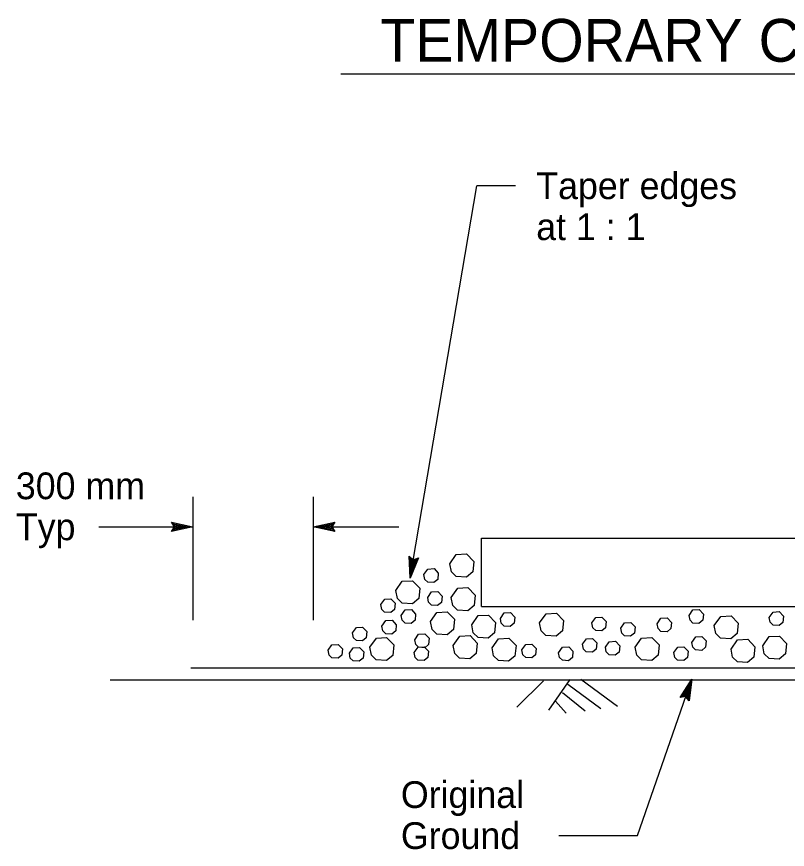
# Model space of a CAD drawing. Extents: x 6707406 to 6714471, y 1868570 to 1872341.
# Drawn here: x 6709477.5 to 6709685, y 1869798.5 to 1870022.7 of the extents above; entities that cross this region are included whole.
import ezdxf

# ---------------------------------------------------------------- set-up
doc = ezdxf.new("R2010")
doc.units = 0
for name, color, linetype in [('56 Stg 3 Anno', 7, 'Continuous'), ('57 Undefined', 7, 'Continuous'), ('59 Soundwall Ann', 7, 'Continuous'), ('60 Nongeo Data', 7, 'Continuous')]:
    doc.layers.add(name, color=color, linetype=linetype)

msp = doc.modelspace()

# ---------------------------------------------------------------- linework, layer by layer
at = {"layer": '56 Stg 3 Anno'}
for p, q in [((6709583.47, 1869871.52), (6709601.41, 1869977.17)), ((6709611.8, 1869977.17), (6709601.41, 1869977.17)), ((6709524.96, 1869893.38), (6709524.96, 1869860.25)), ((6709557.38, 1869893.38), (6709557.38, 1869860.25)), ((6709519.97, 1869885.34), (6709519.2, 1869886.62)), ((6709519.2, 1869886.62), (6709519.2, 1869886.62)), ((6709519.2, 1869886.62), (6709524.96, 1869885.34)), ((6709519.41, 1869886.28), (6709523.64, 1869885.34)), ((6709519.64, 1869885.94), (6709522.31, 1869885.34)), ((6709519.81, 1869885.6), (6709520.99, 1869885.34)), ((6709557.38, 1869885.34), (6709563.14, 1869886.61)), ((6709558.72, 1869885.34), (6709562.92, 1869886.27)), ((6709560.04, 1869885.33), (6709562.75, 1869885.94)), ((6709561.36, 1869885.33), (6709562.52, 1869885.59)), ((6709563.14, 1869886.61), (6709562.38, 1869885.34)), ((6709563.14, 1869886.61), (6709563.14, 1869886.61)), ((6709499.65, 1869885.34), (6709524.96, 1869885.34)), ((6709524.96, 1869885.34), (6709519.2, 1869884.06)), ((6709519.2, 1869884.06), (6709519.97, 1869885.34)), ((6709519.2, 1869884.06), (6709519.2, 1869884.06)), ((6709523.63, 1869885.33), (6709519.43, 1869884.4)), ((6709522.31, 1869885.34), (6709519.6, 1869884.74)), ((6709520.99, 1869885.34), (6709519.82, 1869885.08)), ((6709524.96, 1869885.34), (6709524.96, 1869885.34)), ((6709557.38, 1869885.34), (6709580.43, 1869885.34)), ((6709563.14, 1869884.05), (6709557.38, 1869885.34)), ((6709557.38, 1869885.34), (6709557.38, 1869885.34)), ((6709562.94, 1869884.39), (6709558.71, 1869885.34)), ((6709562.71, 1869884.74), (6709560.04, 1869885.33)), ((6709562.54, 1869885.07), (6709561.36, 1869885.33)), ((6709562.38, 1869885.34), (6709563.14, 1869884.05)), ((6709563.14, 1869884.05), (6709563.14, 1869884.05)), ((6709583.47, 1869871.52), (6709583.17, 1869877.41)), ((6709583.17, 1869877.41), (6709583.17, 1869877.41)), ((6709583.17, 1869877.41), (6709584.3, 1869876.44)), ((6709585.7, 1869876.99), (6709583.47, 1869871.52)), ((6709583.69, 1869872.84), (6709583.48, 1869877.13)), ((6709585.33, 1869876.84), (6709583.69, 1869872.83)), ((6709583.91, 1869874.14), (6709583.78, 1869876.91)), ((6709584.95, 1869876.67), (6709583.91, 1869874.14)), ((6709584.14, 1869875.44), (6709584.08, 1869876.63)), ((6709584.3, 1869876.44), (6709585.7, 1869876.99)), ((6709585.7, 1869876.99), (6709585.7, 1869876.99)), ((6709584.6, 1869876.56), (6709584.14, 1869875.44)), ((6709583.47, 1869871.52), (6709583.47, 1869871.52)), ((6709644.67, 1869802.22), (6709659.29, 1869844.37)), ((6709656.19, 1869839.35), (6709659.29, 1869844.37)), ((6709656.58, 1869839.44), (6709658.85, 1869843.12)), ((6709658.85, 1869843.11), (6709658.36, 1869838.84)), ((6709659.29, 1869844.37), (6709658.61, 1869838.51)), ((6709659.29, 1869844.37), (6709659.29, 1869844.37)), ((6709656.98, 1869839.54), (6709658.42, 1869841.87)), ((6709658.42, 1869841.87), (6709658.1, 1869839.11)), ((6709657.65, 1869839.66), (6709656.19, 1869839.35)), ((6709656.19, 1869839.35), (6709656.19, 1869839.35)), ((6709657.35, 1869839.59), (6709657.98, 1869840.62)), ((6709658.61, 1869838.51), (6709657.65, 1869839.66)), ((6709657.98, 1869840.62), (6709657.84, 1869839.44)), ((6709658.61, 1869838.51), (6709658.61, 1869838.51)), ((6709623.47, 1869802.22), (6709644.67, 1869802.22))]:
    msp.add_line(p, q, dxfattribs=at)
at = {"layer": '57 Undefined'}
msp.add_line((6709564.84, 1870007.33), (6709984.75, 1870007.33), dxfattribs=at)
at = {"layer": '59 Soundwall Ann'}
for p, q in [((6709619.34, 1869843.9), (6709612.17, 1869836.78)), ((6709626.49, 1869844.23), (6709620.7, 1869835.99)), ((6709625.94, 1869843.01), (6709634.84, 1869836.46)), ((6709629.39, 1869844.36), (6709639.34, 1869837.03)), ((6709624.5, 1869840.75), (6709630.61, 1869835.77)), ((6709622.56, 1869838.37), (6709625.47, 1869835.17))]:
    msp.add_line(p, q, dxfattribs=at)
at = {"layer": '60 Nongeo Data'}
for p, q in [((6709602.72, 1869863.92), (6709602.72, 1869882.28)), ((6709602.72, 1869882.28), (6709947.32, 1869882.28)), ((6709602.72, 1869863.92), (6709756.24, 1869863.92)), ((6709524.37, 1869847.39), (6709755.52, 1869847.39)), ((6709502.72, 1869844.14), (6709754.44, 1869844.14))]:
    msp.add_line(p, q, dxfattribs=at)
for points in [[(6709594.15, 1869875.41), (6709595.89, 1869877.88), (6709598.67, 1869878.04), (6709600.6, 1869876.04), (6709600.32, 1869873.24), (6709598.6, 1869871.81), (6709595.86, 1869872.01), (6709594.57, 1869873.26), (6709594.15, 1869875.41)], [(6709587.18, 1869872.5), (6709588.23, 1869873.98), (6709589.89, 1869874.08), (6709591.05, 1869872.87), (6709590.88, 1869871.19), (6709589.85, 1869870.34), (6709588.21, 1869870.45), (6709587.43, 1869871.2), (6709587.18, 1869872.5)], [(6709579.62, 1869868.2), (6709581.36, 1869870.67), (6709584.14, 1869870.83), (6709586.07, 1869868.83), (6709585.79, 1869866.02), (6709584.07, 1869864.6), (6709581.33, 1869864.8), (6709580.04, 1869866.05), (6709579.62, 1869868.2)], [(6709588.2, 1869866.31), (6709589.24, 1869867.8), (6709590.91, 1869867.89), (6709592.07, 1869866.69), (6709591.9, 1869865.01), (6709590.87, 1869864.15), (6709589.22, 1869864.27), (6709588.45, 1869865.02), (6709588.2, 1869866.31)], [(6709594.53, 1869866.33), (6709596.27, 1869868.81), (6709599.04, 1869868.97), (6709600.98, 1869866.97), (6709600.7, 1869864.16), (6709598.98, 1869862.73), (6709596.24, 1869862.93), (6709594.95, 1869864.18), (6709594.53, 1869866.33)], [(6709575.57, 1869864.41), (6709576.61, 1869865.89), (6709578.28, 1869865.99), (6709579.44, 1869864.78), (6709579.27, 1869863.1), (6709578.24, 1869862.25), (6709576.59, 1869862.36), (6709575.82, 1869863.11), (6709575.57, 1869864.41)], [(6709581.08, 1869861.48), (6709582.13, 1869862.97), (6709583.79, 1869863.06), (6709584.95, 1869861.86), (6709584.78, 1869860.18), (6709583.76, 1869859.32), (6709582.11, 1869859.44), (6709581.34, 1869860.19), (6709581.09, 1869861.48)], [(6709588.95, 1869859.84), (6709590.69, 1869862.31), (6709593.46, 1869862.47), (6709595.39, 1869860.47), (6709595.12, 1869857.66), (6709593.4, 1869856.23), (6709590.66, 1869856.43), (6709589.37, 1869857.69), (6709588.95, 1869859.84)], [(6709600.04, 1869858.97), (6709601.78, 1869861.44), (6709604.56, 1869861.6), (6709606.49, 1869859.6), (6709606.21, 1869856.8), (6709604.5, 1869855.37), (6709601.75, 1869855.57), (6709600.46, 1869856.82), (6709600.05, 1869858.97)], [(6709607.75, 1869860.68), (6709608.79, 1869862.16), (6709610.46, 1869862.26), (6709611.61, 1869861.06), (6709611.45, 1869859.38), (6709610.42, 1869858.52), (6709608.77, 1869858.64), (6709608, 1869859.39), (6709607.75, 1869860.68)], [(6709618.33, 1869859.48), (6709620.07, 1869861.95), (6709622.84, 1869862.11), (6709624.77, 1869860.11), (6709624.5, 1869857.3), (6709622.78, 1869855.88), (6709620.04, 1869856.08), (6709618.75, 1869857.33), (6709618.33, 1869859.48)], [(6709632.41, 1869859.47), (6709633.45, 1869860.95), (6709635.12, 1869861.05), (6709636.27, 1869859.85), (6709636.11, 1869858.16), (6709635.08, 1869857.31), (6709633.43, 1869857.43), (6709632.66, 1869858.18), (6709632.41, 1869859.47)], [(6709658.57, 1869861.48), (6709659.61, 1869862.97), (6709661.28, 1869863.06), (6709662.44, 1869861.86), (6709662.27, 1869860.18), (6709661.24, 1869859.32), (6709659.59, 1869859.44), (6709658.82, 1869860.19), (6709658.57, 1869861.48)], [(6709665.35, 1869858.75), (6709667.09, 1869861.23), (6709669.87, 1869861.39), (6709671.8, 1869859.38), (6709671.52, 1869856.58), (6709669.8, 1869855.15), (6709667.06, 1869855.35), (6709665.77, 1869856.6), (6709665.35, 1869858.75)], [(6709680.16, 1869860.93), (6709681.21, 1869862.41), (6709682.87, 1869862.51), (6709684.03, 1869861.3), (6709683.86, 1869859.62), (6709682.84, 1869858.77), (6709681.19, 1869858.88), (6709680.42, 1869859.63), (6709680.17, 1869860.93)], [(6709575.87, 1869858.61), (6709576.91, 1869860.1), (6709578.58, 1869860.19), (6709579.74, 1869858.99), (6709579.57, 1869857.31), (6709578.54, 1869856.45), (6709576.89, 1869856.57), (6709576.12, 1869857.32), (6709575.87, 1869858.61)], [(6709640.17, 1869858.04), (6709641.21, 1869859.52), (6709642.88, 1869859.62), (6709644.04, 1869858.42), (6709643.87, 1869856.74), (6709642.84, 1869855.88), (6709641.19, 1869856), (6709640.42, 1869856.75), (6709640.17, 1869858.04)], [(6709649.97, 1869859.24), (6709651.01, 1869860.73), (6709652.68, 1869860.82), (6709653.84, 1869859.62), (6709653.67, 1869857.94), (6709652.64, 1869857.08), (6709651, 1869857.2), (6709650.22, 1869857.95), (6709649.97, 1869859.24)], [(6709567.96, 1869856.78), (6709569, 1869858.26), (6709570.67, 1869858.36), (6709571.83, 1869857.16), (6709571.66, 1869855.48), (6709570.63, 1869854.62), (6709568.99, 1869854.74), (6709568.21, 1869855.49), (6709567.96, 1869856.78)], [(6709584.71, 1869854.95), (6709585.75, 1869856.44), (6709587.42, 1869856.53), (6709588.58, 1869855.33), (6709588.41, 1869853.65), (6709587.38, 1869852.79), (6709585.74, 1869852.91), (6709584.96, 1869853.66), (6709584.71, 1869854.95)], [(6709572.62, 1869852.91), (6709574.36, 1869855.39), (6709577.13, 1869855.55), (6709579.07, 1869853.54), (6709578.79, 1869850.74), (6709577.07, 1869849.31), (6709574.33, 1869849.51), (6709573.04, 1869850.76), (6709572.62, 1869852.91)], [(6709595.08, 1869853.42), (6709596.82, 1869855.9), (6709599.59, 1869856.06), (6709601.52, 1869854.06), (6709601.25, 1869851.25), (6709599.53, 1869849.82), (6709596.79, 1869850.02), (6709595.5, 1869851.27), (6709595.08, 1869853.42)], [(6709605.52, 1869852.73), (6709607.26, 1869855.2), (6709610.04, 1869855.36), (6709611.97, 1869853.36), (6709611.69, 1869850.55), (6709609.98, 1869849.13), (6709607.23, 1869849.33), (6709605.94, 1869850.58), (6709605.52, 1869852.73)], [(6709629.87, 1869853.73), (6709630.91, 1869855.21), (6709632.58, 1869855.31), (6709633.74, 1869854.11), (6709633.57, 1869852.42), (6709632.54, 1869851.57), (6709630.89, 1869851.68), (6709630.12, 1869852.44), (6709629.87, 1869853.73)], [(6709636.03, 1869852.94), (6709637.08, 1869854.42), (6709638.74, 1869854.52), (6709639.9, 1869853.32), (6709639.73, 1869851.63), (6709638.7, 1869850.78), (6709637.06, 1869850.9), (6709636.28, 1869851.65), (6709636.03, 1869852.94)], [(6709644.06, 1869852.94), (6709645.8, 1869855.41), (6709648.58, 1869855.57), (6709650.51, 1869853.57), (6709650.23, 1869850.76), (6709648.51, 1869849.34), (6709645.77, 1869849.54), (6709644.48, 1869850.79), (6709644.06, 1869852.94)], [(6709659.31, 1869854.23), (6709660.36, 1869855.71), (6709662.02, 1869855.81), (6709663.18, 1869854.61), (6709663.01, 1869852.93), (6709661.98, 1869852.07), (6709660.34, 1869852.19), (6709659.56, 1869852.94), (6709659.31, 1869854.23)], [(6709669.86, 1869852.42), (6709671.6, 1869854.9), (6709674.38, 1869855.06), (6709676.31, 1869853.06), (6709676.03, 1869850.25), (6709674.32, 1869848.82), (6709671.57, 1869849.02), (6709670.28, 1869850.27), (6709669.86, 1869852.42)], [(6709678.39, 1869853.31), (6709680.13, 1869855.78), (6709682.9, 1869855.94), (6709684.83, 1869853.94), (6709684.55, 1869851.13), (6709682.84, 1869849.71), (6709680.1, 1869849.9), (6709678.81, 1869851.16), (6709678.39, 1869853.31)], [(6709561.38, 1869852.11), (6709562.42, 1869853.59), (6709564.09, 1869853.69), (6709565.25, 1869852.49), (6709565.08, 1869850.8), (6709564.05, 1869849.95), (6709562.41, 1869850.07), (6709561.63, 1869850.82), (6709561.38, 1869852.11)], [(6709567.1, 1869851.29), (6709568.14, 1869852.77), (6709569.81, 1869852.87), (6709570.97, 1869851.66), (6709570.8, 1869849.98), (6709569.77, 1869849.13), (6709568.13, 1869849.24), (6709567.35, 1869850), (6709567.1, 1869851.29)], [(6709584.54, 1869851.49), (6709585.58, 1869852.97), (6709587.25, 1869853.07), (6709588.41, 1869851.86), (6709588.24, 1869850.18), (6709587.21, 1869849.33), (6709585.56, 1869849.44), (6709584.79, 1869850.2), (6709584.54, 1869851.49)], [(6709613.55, 1869852.21), (6709614.59, 1869853.7), (6709616.26, 1869853.79), (6709617.42, 1869852.59), (6709617.25, 1869850.91), (6709616.22, 1869850.05), (6709614.57, 1869850.17), (6709613.8, 1869850.92), (6709613.55, 1869852.21)], [(6709623.44, 1869851.45), (6709624.49, 1869852.94), (6709626.15, 1869853.03), (6709627.31, 1869851.83), (6709627.14, 1869850.15), (6709626.11, 1869849.29), (6709624.47, 1869849.41), (6709623.7, 1869850.16), (6709623.44, 1869851.45)], [(6709654.45, 1869851.49), (6709655.5, 1869852.97), (6709657.16, 1869853.07), (6709658.32, 1869851.87), (6709658.15, 1869850.18), (6709657.12, 1869849.33), (6709655.48, 1869849.44), (6709654.71, 1869850.2), (6709654.45, 1869851.49)]]:
    msp.add_lwpolyline(points, dxfattribs=at)

# ---------------------------------------------------------------- texts
at = {"layer": '57 Undefined'}
for s, height, p in [('TEMPORARY CONSTRUCTION ENTRANCE (TYPE 2)', 11.5203, (6709575.42, 1870010.55)), ('Taper edges', 7.2002, (6709617.42, 1869973.57)), ('at 1 : 1', 7.2, (6709617.42, 1869962.53)), ('300 mm', 7.2, (6709477.29, 1869892.78)), ('Typ', 7.2, (6709477.29, 1869881.74)), ('Original', 7.2, (6709580.97, 1869809.65)), ('Ground', 7.2, (6709580.97, 1869798.61))]:
    msp.add_text(s, height=height, dxfattribs=at).set_placement(p)

doc.saveas('drawing.dxf')
